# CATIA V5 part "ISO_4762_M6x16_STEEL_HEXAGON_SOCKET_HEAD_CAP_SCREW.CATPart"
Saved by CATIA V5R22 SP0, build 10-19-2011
Part number: ISO 4762 SCREW M6x16 STEEL HEXAGON SOCKET HEAD CAP
Publications: "Mating Face", "Axis"
Bounding box of the stored display mesh (mm): x -16 to 6, y -5 to 5, z -4.99 to 4.99
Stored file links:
  D:\PER\CAO_PER_MODIF_2025\CAO_PER_pick&place_2024P\ISO_4762_M6x16_STEEL_HEXAGON_SOCKET_HEAD_CAP_SCREW.CATPart
  C:\Program Files\Dassault Systemes\B22\win_b64\startup\components\MechanicalStandardParts\EN_Standards\Design_Tables\EN_ISO_4762_HEXAGON_SOCKET_HEAD_CAP_SCREW.txt
  C:\Program Files\Dassault Systemes\B22\win_b64\startup\components\MechanicalStandardParts\ISO_Standards\Design_Tables\ISO_4762_HEXAGON_SOCKET_HEAD_CAP_SCREW.txt
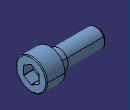
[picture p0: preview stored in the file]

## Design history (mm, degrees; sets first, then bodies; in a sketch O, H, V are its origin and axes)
Parameters
  d_dia = 6 mm
  l_nom = 16 mm
  k_head_depth_max = 6 mm
  s_nom = 5 mm
  r_min = 0.25 mm
  ds_max = 6 mm
  e = 5.723 mm
  t_min = 3 mm
  p_pitch = 1 mm
  Threading = 13 mm
  dk_max = 10 mm
Body1 "PartBody" (main body)
  Sketch1 on yz-plane, origin (0, 0, 0), H (0, 1, 0), V (0, 0, 1)
    circle A1 centre (0, 0) radius 5
    radius A1 = 5 {= dk_max /2}
  Pad1: profile Sketch1, direction (1, 0, 0), length 6 {= k_head_depth_max}
  Fillet1: radius 0.25 {= r_min}, on edge [face of Pad1 | face of Pad1]
  Body2
    Sketch2 on face of Pad1, origin (6, 0, 0), H (0, 1, 0), V (0, 0, 1)
      point P1 (2.5, -1.4434)
      point P2 (2.5, 1.4434)
      point P3 (0, 2.8868)
      point P4 (-2.5, 1.4434)
      point P5 (-2.5, -1.4434)
      point P6 (0, -2.8868)
      point P7 (2.5, 0)
      line L1 (2.5, -1.4434) -> (2.5, 1.4434)
      line L2 (2.5, 1.4434) -> (0, 2.8868)
      line L3 (0, 2.8868) -> (-2.5, 1.4434)
      line L4 (-2.5, 1.4434) -> (-2.5, -1.4434)
      line L5 (-2.5, -1.4434) -> (0, -2.8868)
      line L6 (0, -2.8868) -> (2.5, -1.4434)
      construction line L7 (0, 0) -> (2.5, 0)
      construction circle A1 centre (0, 0) radius 2.8868
      construction arc A2 centre (-2.5, -1.4434) radius 2.8868 from (-2.5, 1.4434) to (0, -2.8868) cw
      construction arc A3 centre (2.5, 1.4434) radius 2.8868 from (0, 2.8868) to (2.5, -1.4434) ccw
      point P8 (-2.5, -1.4434)
      point P9 (2.5, 1.4434)
      distance L1 L4 = 5 {= s_nom}
      horizontal: L7 H
      coincidence: A1 P1, A1 P2, A1 P3, A1 P4, A1 P5, A1 P6, A2 P4, A2 P6, A2 O, P8 P5, A3 P3, A3 P1, A3 O, P9 P2
      midpoint: P7 L1
    Pad2: profile Sketch2, direction (-1, 0, 0), length 4.6493 {= t_min +(e /3.47)}
    Body3
      Sketch3 on zx-plane, origin (0, 0, 0), H (-1, 0, 0), V (0, 0, 1)
        point P1 (-1.3479, 0)
        line L1 (-1.3479, 0) -> (-3, 2.8615)
        line L2 (-3, 2.8615) -> (-6, 2.8615)
        line L3 (-6, 2.8615) -> (-6, 0)
        axis line L4 (-46.2384, 0) -> (26.3409, 0)
        reference projected line E1 (-6, -6.9227) -> (-6, 6.9227) from edge [face of Pad2 | face of Pad2]
        length L2 = 3 {= t_min}
        angle L1 L4 = 60
        distance L2 L4 = 2.8615 {= e /2}
        horizontal: L2 H, L4 H
        perpendicularity: L3 L2
        fix: L4
        coincidence: L3 E1, P1 L4
      Shaft1: profile Sketch3, axis Sketch3.L4, angle 360
    Intersect1: tool Body3
  Remove1: tool Body2
  Sketch4 on xy-plane, origin (0, 0, 0), H (1, 0, 0), V (0, 1, 0)
    line L1 (0, 0) -> (0, 3)
    line L2 (0, 3) -> (-3, 3)
    line L3 (-3, 3) -> (-3, 2.9268)
    line L4 (-3, 2.9268) -> (-16, 2.9268)
    line L5 (-16, 2.9268) -> (-16, 0)
    axis line L6 (-192.3446, 0) -> (99.1594, 0)
    distance L5 L1 = 16 {= l_nom}
    distance L3 L5 = 13 {= Threading}
    distance L2 L6 = 3 {= ds_max /2}
    distance L4 L6 = 2.9268 {= d_dia /2.05}
    vertical: L1 V, L3 V, L5 V
    horizontal: L2 H, L4 H, L6 H
    fix: L6
  Shaft2: profile Sketch4, axis Sketch4.L6, angle 360
  Fillet2: radius 0.25 {= r_min}, on edge [face of Shaft2 | face of Pad1]
  Chamfer1: length 1 {= p_pitch}, angle 45, on edge [face of Shaft2 | face of Shaft2]
  Thread1: diameter 5.8537 {= d_dia /1.025}, depth 13 {= Threading}, pitch 1, on face of Shaft2, from face of Shaft2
